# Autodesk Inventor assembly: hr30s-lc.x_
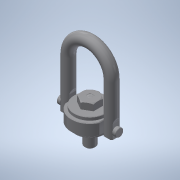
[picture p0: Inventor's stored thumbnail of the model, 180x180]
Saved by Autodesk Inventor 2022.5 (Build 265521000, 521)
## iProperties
Part Number: hr30s-lc.x_
Material: 一般
Document SubType Name: Assembly
Designer: ImaoCorp
Sending System: SOLIDWORKS 2017-2017317
MC: AMD64
MC_MODEL: Intel64 Family 6 Model 60 Stepping 3, GenuineIntel
OS: Windows_NT
FRU: Parasolid Version 29.0, build 201,  4-17-2017
FORMAT: text
GUISE: transmit
KEY: hr30s-lc
FILE: hr30s-lc.x_t
DATE: Mon Jul 01 17:38:13 2019
Author: ImaoCorp
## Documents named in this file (3)
- X:\14_SW2022-Inv2022\00_全2023-1023新製品(TCC)まで\h\hr30s-lc\HR30S-LC.iam
- X:\14_SW2022-Inv2022\00_全2023-1023新製品(TCC)まで\h\hr30s-lc\hr30s-lc_01.ipt
- X:\14_SW2022-Inv2022\00_全2023-1023新製品(TCC)まで\h\hr30s-lc\hr30s-lc_02.ipt
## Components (2 placed, 2 different names)
1. hr30s-lc_01
2. hr30s-lc_02
